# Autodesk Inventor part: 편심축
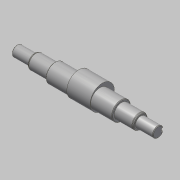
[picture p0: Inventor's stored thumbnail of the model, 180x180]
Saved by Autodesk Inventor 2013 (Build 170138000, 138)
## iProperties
Created: 2015-10
Part Number: 편심축
Document SubType Name: Modeling
Designer: mdu
Density: 1 g/cm^3
Material: 강철, 연강
Mass: 168.947 g
Surface Area: 248.524 cm^2
Volume: 168.947 cm^3
Author: mdu
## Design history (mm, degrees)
sketch "스케치1"
  geometry: L1 (-20.5, -41.331)-(-20.5, 32.669) reference; L2 (7.5, -30.031)-(7.5, 21.369) reference; L3 (135.5, -30.331)-(135.5, 21.669) reference; L4 (121.5, 21.369)-(121.5, -30.031) reference; L5 (184.5, -4.331)-(-57.5, -4.331); L6 (184.5, -4.331)-(184.5, 4.669); L7 (154.5, 8.169)-(121.5, 8.169); L8 (121.5, 8.169)-(121.5, 11.669); L9 (121.5, 11.669)-(7.5, 11.669); L10 (7.5, 11.669)-(7.5, 8.169); L11 (7.5, 8.169)-(-27.5, 8.169); L12 (-27.5, 8.169)-(-27.5, 4.669); L13 (-27.5, 4.669)-(-57.5, 4.669); L14 (-57.5, 4.669)-(-57.5, -4.331); L15 (154.5, 8.169)-(154.5, 4.669); L16 (154.5, 4.669)-(184.5, 4.669); C1 r 32.5 at (64.5, -4.331) reference; 1 further point
  constraints: 24 end point, 8 perpendicular, 5 point on line, 3 parallel, 2 collinear
  dimensions: "d1" = 25 diameter of L11 L5; "d2" = 32 diameter of L9 L5; "d3" = 18 diameter of L13 L5; "d4" = 35 distance of L10.end L11.end; "d5" = 30 distance of L12.end L13.end; "d15" = 33 distance of L7.start L7.end; "d26" = 30 distance of L15.end L6.end
revolve "회전1" sketch "스케치1" stored, may be unused: angle "d6" = 90 deg
node "작업 평면1"
sketch "스케치2"
  geometry: C1 r 16 at (0, 0) reference; C2 r 20.75 at (0, 4)
  constraints: 1 centre point, 1 vertical alignment
  dimensions: "d34" = 4 distance of C2.centre C1.centre; "d35" = 41.5 diameter of C2
extrude "돌출1" join sketch "스케치2" stored distance "d9" = 40; taper "d10" = 0 deg
chamfer "모따기1" distance "d11" = 1; stored, may be unused: second distance "d12" = 2, angle "d13" = 45 deg
node "작업 평면2"
sketch "스케치3"
  geometry: L1 (-15, -8)-(-15, 8) reference; L2 (-15, 3)-(0, 3); L3 (0, -3)-(-15, -3); A1 r 3 centre (0, 0) between (0, -3) and (0, 3); 2 further points
  constraints: 4 end point, 2 perpendicular, 2 point on circle, 2 point on line, 2 tangent, 1 centre point, 1 horizontal alignment, 1 midpoint
  dimensions: "d16" = 18 dimension on A1 L1; "d17" = 6 distance between parallel lines of L3 L2
extrude "돌출2" cut sketch "스케치3" distance "d18" = 3.5; taper "d19" = 0 deg
node "작업 평면3"
chamfer "모따기2" distance "d36" = 2.2; stored, may be unused: second distance "d37" = 2, angle "d38" = 30 deg
chamfer "모따기3" distance "d39" = 2.2; stored, may be unused: second distance "d40" = 2, angle "d41" = 30 deg
fillet "모깎기1" dims "d42" = 1, "d43" = 2
fillet "모깎기2" dims "d44" = 1, "d45" = 2
node "솔리드1"
mirror "대칭1"
node "참조1"
node "참조2"
node "참조3"
node "참조4"
node "참조5"
other parameters: "d30" = 35
